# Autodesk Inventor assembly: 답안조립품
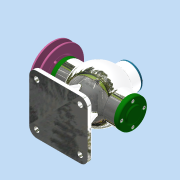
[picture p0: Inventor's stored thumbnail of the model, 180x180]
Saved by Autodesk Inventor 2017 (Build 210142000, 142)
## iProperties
Part Number: 답안조립품
Material: 일반
Document SubType Name: Assembly
Designer: MRC
Author: MRC
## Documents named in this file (16)
- C:\Users\MRC\Desktop\강민수\720811V1010\답안조립품.iam
- C:\Users\MRC\Desktop\강민수\720811V1010\본체.ipt
- C:\Users\MRC\Desktop\강민수\720811V1010\V-벨트풀리.ipt
- C:\Users\MRC\Desktop\강민수\720811V1010\너트 M8.ipt
- C:\Users\MRC\Desktop\강민수\720811V1010\뒤커버.ipt
- C:\Users\MRC\Desktop\강민수\720811V1010\베어링- 6202.ipt
- KS B 2023 - 6202 - 15 x 35 x 11 - 7.8.ipt
- C:\Users\MRC\Desktop\강민수\720811V1010\볼트 M4 x 12.ipt
- C:\Users\MRC\Desktop\강민수\720811V1010\볼트 M4 x 16.ipt
- C:\Users\MRC\Desktop\강민수\720811V1010\상부커버.ipt
- C:\Users\MRC\Desktop\강민수\720811V1010\슬라이드.ipt
- C:\Users\MRC\Desktop\강민수\720811V1010\앞커버.ipt
- C:\Users\MRC\Desktop\강민수\720811V1010\오일실 15 30 7.ipt
- C:\Users\MRC\Desktop\강민수\720811V1010\칼라.ipt
- C:\Users\MRC\Desktop\강민수\720811V1010\키 4 x 4 x 12.ipt
- C:\Users\MRC\Desktop\강민수\720811V1010\편심축.ipt
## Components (15 placed, 4 different names)
1. V-벨트풀리:1
2. KS B 2023 - 6202 - 15 x 35 x 11 - 7.8:1
3. KS B 2023 - 6202 - 15 x 35 x 11 - 7.8:2
4. KS B 1021 - 에 따름 ISO 1207 - 미터 A  M 4 x 12:1
5. KS B 1021 - 에 따름 ISO 1207 - 미터 A  M 4 x 12:2
6. KS B 1021 - 에 따름 ISO 1207 - 미터 A  M 4 x 12:3
7. KS B 1021 - 에 따름 ISO 1207 - 미터 A  M 4 x 12:4
8. ISO 4762 M4 x 16:1
9. ISO 4762 M4 x 16:3
10. ISO 4762 M4 x 16:4
11. ISO 4762 M4 x 16:5
12. ISO 4762 M4 x 16:2
13. ISO 4762 M4 x 16:6
14. ISO 4762 M4 x 16:7
15. ISO 4762 M4 x 16:8
